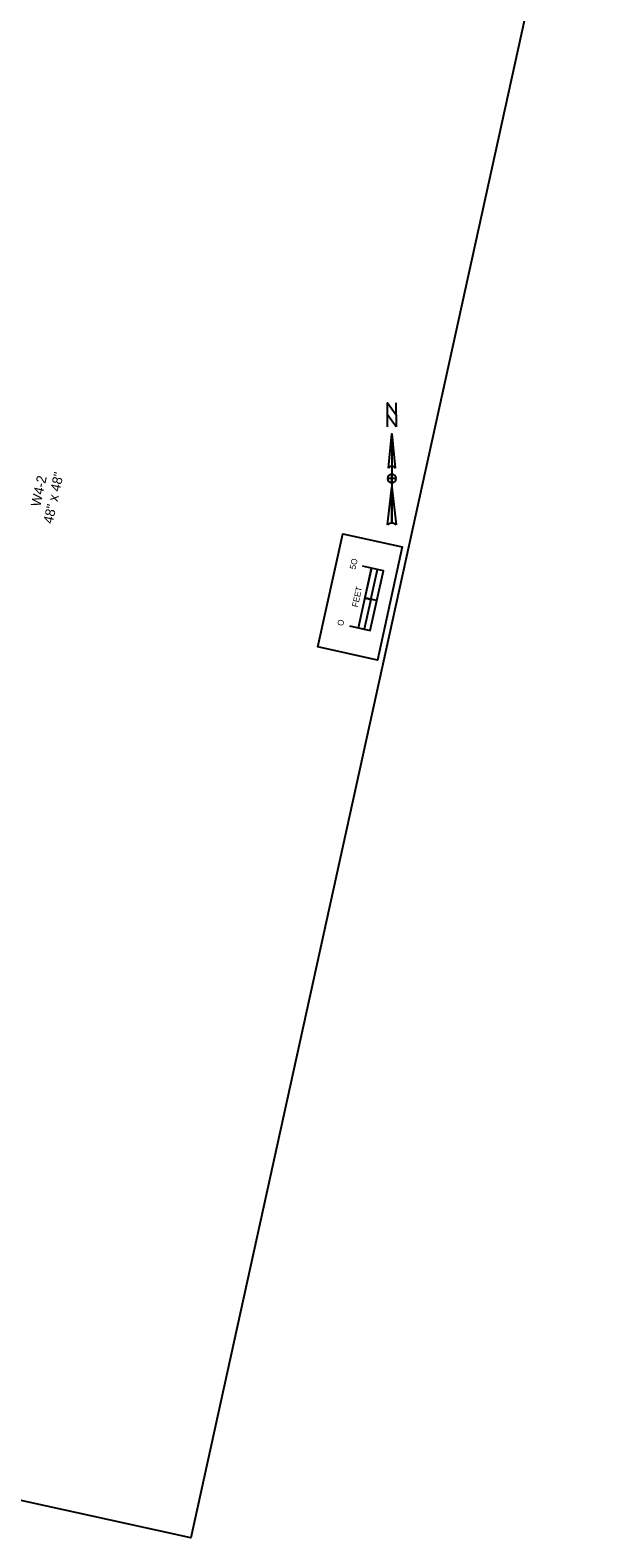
# Model space of a CAD drawing. Extents: x 14104283 to 14129344, y 8637090 to 8673339.
# Drawn here: x 14107780 to 14108248, y 8637090 to 8638327 of the extents above; entities that cross this region are included whole.
import ezdxf

# ---------------------------------------------------------------- set-up
doc = ezdxf.new("R2010")
doc.units = 0
for name, color, linetype in [('Cell', 7, 'Continuous'), ('dsnCellsNorthArrow', 7, 'Continuous'), ('dsnCellsScaleBlock', 7, 'Continuous'), ('dsnNonPlotable', 7, 'Continuous')]:
    doc.layers.add(name, color=color, linetype=linetype)

msp = doc.modelspace()

# ---------------------------------------------------------------- linework, layer by layer
at = {"layer": 'dsnCellsNorthArrow'}
for p, q in [((14108076.4, 8637995.7), (14108079.2, 8637967.5)), ((14108076.4, 8637995.7), (14108076.4, 8637922.4)), ((14108073.6, 8637967.5), (14108073.6, 8637967.5)), ((14108073.7, 8637967.8), (14108074.2, 8637968.4)), ((14108072.9, 8637921), (14108076.4, 8637952)), ((14108076.4, 8637955.5), (14108076.4, 8637955.5))]:
    msp.add_line(p, q, dxfattribs=at)
msp.add_lwpolyline([(14108079.9, 8638001.3), (14108072.9, 8638011.2), (14108072.9, 8638021), (14108079.9, 8638011.2)], close=True, dxfattribs=at)
for points in [[(14108072.9, 8638001.3), (14108072.9, 8638021), (14108079.9, 8638011.2), (14108079.9, 8638021)], [(14108073.6, 8637967.5), (14108076.4, 8637995.7), (14108076.4, 8637968.9)], [(14108076.4, 8637955.5), (14108076.4, 8637959.1), (14108072.9, 8637959.1)], [(14108079.9, 8637959.1), (14108076.4, 8637959.1), (14108076.4, 8637962.6)], [(14108076.4, 8637922.4), (14108076.4, 8637952), (14108079.9, 8637921)]]:
    msp.add_lwpolyline(points, dxfattribs=at)
for centre, radius, start, end in [((14108076.4, 8637959.1), 3.52, 90, 180), ((14108076.4, 8637959.1), 3.52, 180, 270), ((14108076.4, 8637965.4), 3.52, 90.0204, 143.1257), ((14108076.4, 8637965.4), 3.52, 36.8481, 90.0218), ((14108076.4, 8637959.1), 3.52, 0, 90), ((14108076.4, 8637959.1), 3.52, 270, 360), ((14108076.4, 8637917.3), 5.1, 89.9894, 133.619), ((14108076.4, 8637917.3), 5.11, 46.4021, 90.0006)]:
    msp.add_arc(centre, radius, start, end, dxfattribs=at)
at = {"layer": 'dsnCellsScaleBlock'}
msp.add_line((14108064, 8637858.9), (14108054.2, 8637861), dxfattribs=at)
msp.add_line((14108064, 8637858.9), (14108054.2, 8637861), dxfattribs=at)
for points in [[(14108064.6, 8637810.1), (14108015.7, 8637820.8), (14108036.1, 8637913.6), (14108084.9, 8637902.9)], [(14108015.7, 8637820.8), (14108036.1, 8637913.6), (14108084.9, 8637902.9), (14108064.6, 8637810.1)], [(14108064.6, 8637810.1), (14108015.7, 8637820.8), (14108036.1, 8637913.6), (14108084.9, 8637902.9)], [(14108059.1, 8637859.9), (14108064.5, 8637884.4), (14108059.6, 8637885.4), (14108054.2, 8637861)], [(14108058.6, 8637834.4), (14108064, 8637858.9), (14108059.1, 8637859.9), (14108053.7, 8637835.5)]]:
    msp.add_lwpolyline(points, close=True, dxfattribs=at)
for points in [[(14108041.6, 8637838.2), (14108058.6, 8637834.4), (14108069.4, 8637883.3), (14108052.3, 8637887)], [(14108048.9, 8637836.6), (14108059.6, 8637885.4)]]:
    msp.add_lwpolyline(points, dxfattribs=at)
at = {"layer": 'dsnNonPlotable'}
msp.add_lwpolyline([(14106925, 8637306.7), (14107261.4, 8638837.7), (14108247.8, 8638620.9), (14107911.4, 8637089.9)], close=True, dxfattribs=at)

# ---------------------------------------------------------------- texts
at = {"layer": 'Cell'}
for s, p in [('W4-2', (14107787.8, 8637935.4)), ('48" x 48"', (14107798, 8637921.5))]:
    msp.add_text(s, height=8, rotation=77.6102, dxfattribs=at).set_placement(p)
at = {"layer": 'dsnCellsScaleBlock'}
for s, p in [('5O', (14108046.5, 8637884.1)), ('FEET', (14108048.4, 8637853.1)), ('O', (14108036.3, 8637837.7))]:
    msp.add_text(s, height=5, rotation=77.6078, dxfattribs=at).set_placement(p)

doc.saveas('drawing.dxf')
